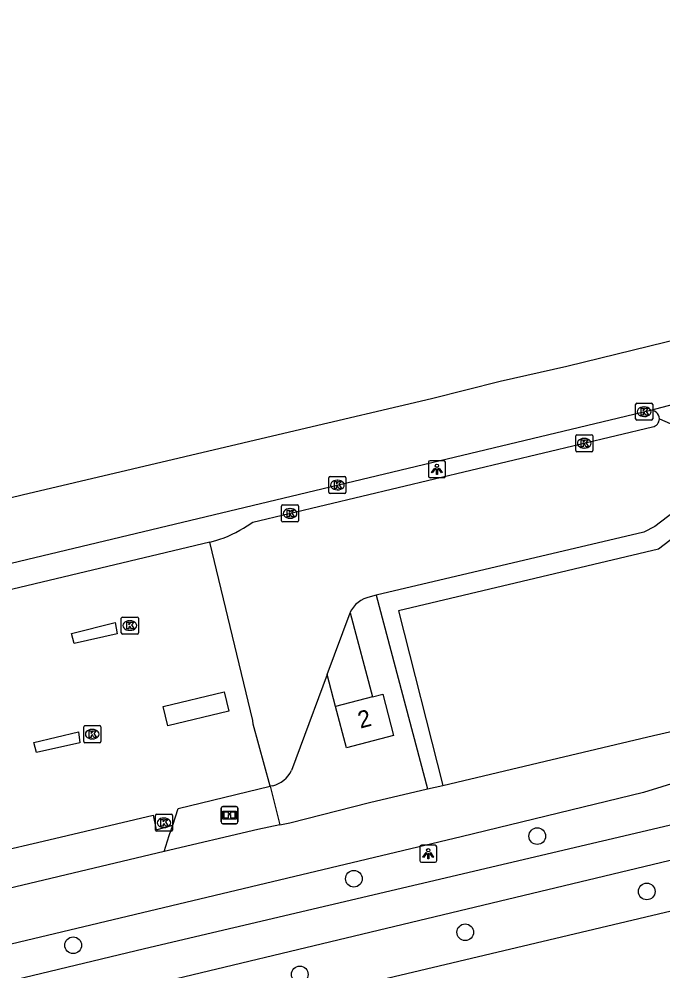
# Model space of a CAD drawing. Extents: x 157663 to 158496, y 379212 to 380934.
# Drawn here: x 158190.6 to 158228.4, y 380874.1 to 380929.9 of the extents above; entities that cross this region are included whole.
import ezdxf

# ---------------------------------------------------------------- set-up
doc = ezdxf.new("R2010")
doc.units = 0
for name, color, linetype in [('IMGEO_Boom', 7, 'Continuous'), ('IMGEO_Fietspad_gesloten', 7, 'Continuous'), ('IMGEO_Groenvoorziening', 7, 'Continuous'), ('IMGEO_Hek', 7, 'Continuous'), ('IMGEO_Informatiebord', 7, 'Continuous'), ('IMGEO_Kolk', 7, 'Continuous'), ('IMGEO_Lichtpunt', 7, 'Continuous'), ('IMGEO_Pand', 7, 'Continuous'), ('IMGEO_Pand_nummerreeks', 7, 'Continuous'), ('IMGEO_Rijbaan_lokaal_gesloten', 7, 'Continuous'), ('IMGEO_Rijbaan_lokaal_open', 7, 'Continuous'), ('IMGEO_Rijbaan_regionaal_gesloten', 7, 'Continuous'), ('IMGEO_Voetpad_halfverhard', 7, 'Continuous'), ('IMGEO_Voetpad_open', 7, 'Continuous')]:
    doc.layers.add(name, color=color, linetype=linetype)

msp = doc.modelspace()

# ---------------------------------------------------------------- linework, layer by layer
at = {"layer": 'IMGEO_Boom'}
for centre in [(158221.018, 380881.956), (158210.269, 380879.461), (158227.432, 380878.713), (158216.797, 380876.321), (158193.821, 380875.556), (158207.103, 380873.852)]:
    msp.add_circle(centre, 0.489, dxfattribs=at)
at = {"layer": 'IMGEO_Fietspad_gesloten'}
for points in [[(158214.584, 380884.721), (158215.49, 380884.935), (158221.487, 380886.347), (158227.823, 380887.854), (158228.952, 380888.114)], [(158234.764, 380886.844), (158227.239, 380884.51), (158216.562, 380881.917), (158176.169, 380872.274), (158170.786, 380871.038), (158169.397, 380870.904), (158167.571, 380870.872), (158165.75, 380871.003), (158163.948, 380871.297), (158155.69, 380872.659), (158150.365, 380873.521), (158148.523, 380873.783), (158145.729, 380873.832), (158142.943, 380873.632), (158141.381, 380873.409), (158125.611, 380869.701)], [(158205.929, 380882.622), (158206.509, 380882.744), (158211.181, 380883.92), (158214.584, 380884.721)], [(158205.929, 380882.622), (158204.633, 380882.349), (158199.155, 380881.064)], [(158199.155, 380881.064), (158186.759, 380878.107)]]:
    msp.add_lwpolyline(points, dxfattribs=at)
at = {"layer": 'IMGEO_Groenvoorziening'}
msp.add_lwpolyline([(158163.827, 380862.151), (158230.016, 380877.859)], dxfattribs=at)
at = {"layer": 'IMGEO_Hek'}
for points in [[(158236.116, 380904.381), (158234.153, 380903.401), (158228.121, 380898.781), (158212.895, 380895.165), (158215.49, 380884.935)], [(158204.633, 380882.349), (158199.155, 380881.064)], [(158199.155, 380881.064), (158186.759, 380878.107)]]:
    msp.add_lwpolyline(points, dxfattribs=at)
at = {"layer": 'IMGEO_Informatiebord'}
for p, q in [((158202.49, 380882.788), (158202.49, 380883.588)), ((158202.49, 380883.588), (158202.49, 380882.788)), ((158202.59, 380883.688), (158203.38, 380883.688)), ((158203.38, 380883.688), (158202.59, 380883.688)), ((158203.48, 380883.588), (158203.48, 380882.788)), ((158203.48, 380882.788), (158203.48, 380883.588)), ((158203.38, 380882.688), (158202.59, 380882.688)), ((158202.59, 380882.688), (158203.38, 380882.688))]:
    msp.add_line(p, q, dxfattribs=at)
for points in [[(158202.591, 380883.42), (158203.379, 380883.42), (158203.379, 380882.956), (158202.591, 380882.956), (158202.591, 380883.42)], [(158202.656, 380883.355), (158202.656, 380883.021), (158202.931, 380883.021), (158202.932, 380883.234), (158203.036, 380883.235), (158203.037, 380883.021), (158203.314, 380883.021), (158203.314, 380883.355), (158203.038, 380883.355), (158203.038, 380883.275), (158202.932, 380883.275), (158202.932, 380883.355), (158202.656, 380883.355)]]:
    msp.add_lwpolyline(points, dxfattribs=at)
for centre, start, end in [((158202.59, 380883.588), 90, 180), ((158202.59, 380883.588), 90, 180), ((158203.38, 380883.588), 0, 90), ((158203.38, 380883.588), 360, 90), ((158202.59, 380882.788), 180, 270), ((158202.59, 380882.788), 180, 270), ((158203.38, 380882.788), 270, 0), ((158203.38, 380882.788), 270, 0)]:
    msp.add_arc(centre, 0.1, start, end, dxfattribs=at)
at = {"layer": 'IMGEO_Kolk'}
for p, q in [((158226.782, 380906.416), (158226.782, 380907.268)), ((158226.857, 380907.342), (158227.709, 380907.342)), ((158227.27, 380907.122), (158227.295, 380907.122)), ((158227.783, 380907.268), (158227.783, 380906.416)), ((158227.293, 380906.562), (158227.268, 380906.562)), ((158227.709, 380906.342), (158226.857, 380906.342)), ((158223.271, 380904.567), (158223.271, 380905.419)), ((158223.346, 380905.493), (158224.198, 380905.493)), ((158224.272, 380905.419), (158224.272, 380904.567)), ((158223.759, 380905.273), (158223.784, 380905.273)), ((158224.198, 380904.493), (158223.346, 380904.493)), ((158223.782, 380904.713), (158223.757, 380904.713)), ((158208.805, 380902.116), (158208.805, 380902.968)), ((158208.88, 380903.042), (158209.732, 380903.042)), ((158209.293, 380902.822), (158209.318, 380902.822)), ((158209.806, 380902.968), (158209.806, 380902.116)), ((158209.732, 380902.042), (158208.88, 380902.042)), ((158209.316, 380902.262), (158209.291, 380902.262)), ((158206.033, 380900.453), (158206.033, 380901.305)), ((158206.108, 380901.379), (158206.96, 380901.379)), ((158206.521, 380901.159), (158206.546, 380901.159)), ((158207.034, 380901.305), (158207.034, 380900.453)), ((158206.96, 380900.379), (158206.108, 380900.379)), ((158206.544, 380900.599), (158206.519, 380900.599)), ((158196.716, 380894.804), (158197.568, 380894.804)), ((158196.641, 380893.878), (158196.641, 380894.73)), ((158197.129, 380894.584), (158197.154, 380894.584)), ((158197.642, 380894.73), (158197.642, 380893.878)), ((158197.568, 380893.804), (158196.716, 380893.804)), ((158197.152, 380894.024), (158197.127, 380894.024)), ((158194.437, 380887.509), (158194.437, 380888.361)), ((158194.512, 380888.435), (158195.364, 380888.435)), ((158194.925, 380888.215), (158194.95, 380888.215)), ((158195.438, 380888.361), (158195.438, 380887.509)), ((158194.948, 380887.655), (158194.923, 380887.655)), ((158195.364, 380887.435), (158194.512, 380887.435)), ((158198.644, 380882.314), (158198.644, 380883.166)), ((158198.719, 380883.24), (158199.571, 380883.24)), ((158199.645, 380883.166), (158199.645, 380882.314)), ((158199.132, 380883.02), (158199.157, 380883.02)), ((158199.571, 380882.24), (158198.719, 380882.24)), ((158199.155, 380882.46), (158199.13, 380882.46))]:
    msp.add_line(p, q, dxfattribs=at)
for points in [[(158226.782, 380906.416), (158226.782, 380907.268)], [(158226.857, 380907.342), (158227.709, 380907.342)], [(158227.103, 380907.042), (158227.226, 380907.042), (158227.226, 380906.891), (158227.356, 380907.042), (158227.52, 380907.042), (158227.374, 380906.891), (158227.527, 380906.642), (158227.375, 380906.642), (158227.29, 380906.806), (158227.226, 380906.739), (158227.226, 380906.642), (158227.103, 380906.642), (158227.103, 380907.042)], [(158227.783, 380907.268), (158227.783, 380906.416)], [(158227.709, 380906.342), (158226.857, 380906.342)], [(158223.271, 380904.567), (158223.271, 380905.419)], [(158223.346, 380905.493), (158224.198, 380905.493)], [(158224.272, 380905.419), (158224.272, 380904.567)], [(158223.592, 380905.193), (158223.715, 380905.193), (158223.715, 380905.042), (158223.845, 380905.193), (158224.009, 380905.193), (158223.863, 380905.042), (158224.016, 380904.793), (158223.864, 380904.793), (158223.779, 380904.957), (158223.715, 380904.89), (158223.715, 380904.793), (158223.592, 380904.793), (158223.592, 380905.193)], [(158224.198, 380904.493), (158223.346, 380904.493)], [(158208.805, 380902.116), (158208.805, 380902.968)], [(158208.88, 380903.042), (158209.732, 380903.042)], [(158209.126, 380902.742), (158209.249, 380902.742), (158209.249, 380902.591), (158209.379, 380902.742), (158209.543, 380902.742), (158209.397, 380902.591), (158209.55, 380902.342), (158209.398, 380902.342), (158209.313, 380902.506), (158209.249, 380902.439), (158209.249, 380902.342), (158209.126, 380902.342), (158209.126, 380902.742)], [(158209.806, 380902.968), (158209.806, 380902.116)], [(158209.732, 380902.042), (158208.88, 380902.042)], [(158206.033, 380900.453), (158206.033, 380901.305)], [(158206.108, 380901.379), (158206.96, 380901.379)], [(158206.354, 380901.079), (158206.477, 380901.079), (158206.477, 380900.928), (158206.607, 380901.079), (158206.771, 380901.079), (158206.625, 380900.928), (158206.778, 380900.679), (158206.626, 380900.679), (158206.541, 380900.843), (158206.477, 380900.776), (158206.477, 380900.679), (158206.354, 380900.679), (158206.354, 380901.079)], [(158207.034, 380901.305), (158207.034, 380900.453)], [(158206.96, 380900.379), (158206.108, 380900.379)], [(158196.716, 380894.804), (158197.568, 380894.804)], [(158196.641, 380893.878), (158196.641, 380894.73)], [(158196.962, 380894.504), (158197.085, 380894.504), (158197.085, 380894.353), (158197.215, 380894.504), (158197.379, 380894.504), (158197.233, 380894.353), (158197.386, 380894.104), (158197.234, 380894.104), (158197.149, 380894.268), (158197.085, 380894.201), (158197.085, 380894.104), (158196.962, 380894.104), (158196.962, 380894.504)], [(158197.642, 380894.73), (158197.642, 380893.878)], [(158197.568, 380893.804), (158196.716, 380893.804)], [(158194.437, 380887.509), (158194.437, 380888.361)], [(158194.512, 380888.435), (158195.364, 380888.435)], [(158194.758, 380888.135), (158194.881, 380888.135), (158194.881, 380887.984), (158195.011, 380888.135), (158195.175, 380888.135), (158195.029, 380887.984), (158195.182, 380887.735), (158195.03, 380887.735), (158194.945, 380887.899), (158194.881, 380887.832), (158194.881, 380887.735), (158194.758, 380887.735), (158194.758, 380888.135)], [(158195.438, 380888.361), (158195.438, 380887.509)], [(158195.364, 380887.435), (158194.512, 380887.435)], [(158198.644, 380882.314), (158198.644, 380883.166)], [(158198.719, 380883.24), (158199.571, 380883.24)], [(158199.645, 380883.166), (158199.645, 380882.314)], [(158198.965, 380882.94), (158199.088, 380882.94), (158199.088, 380882.789), (158199.218, 380882.94), (158199.382, 380882.94), (158199.236, 380882.789), (158199.389, 380882.54), (158199.237, 380882.54), (158199.152, 380882.704), (158199.088, 380882.637), (158199.088, 380882.54), (158198.965, 380882.54), (158198.965, 380882.94)], [(158199.571, 380882.24), (158198.719, 380882.24)]]:
    msp.add_lwpolyline(points, dxfattribs=at)
for centre, start, end in [((158226.859, 380907.266), 91.552, 178.448), ((158226.859, 380907.266), 91.552, 178.448), ((158227.707, 380907.266), 1.552, 88.448), ((158227.707, 380907.266), 1.552, 88.448), ((158226.859, 380906.418), 181.552, 268.448), ((158226.859, 380906.418), 181.552, 268.448), ((158227.707, 380906.418), 271.552, 358.448), ((158227.707, 380906.418), 271.552, 358.448), ((158223.348, 380905.417), 91.552, 178.448), ((158223.348, 380905.417), 91.552, 178.448), ((158224.196, 380905.417), 1.552, 88.448), ((158224.196, 380905.417), 1.552, 88.448), ((158223.348, 380904.569), 181.552, 268.448), ((158223.348, 380904.569), 181.552, 268.448), ((158224.196, 380904.569), 271.552, 358.448), ((158224.196, 380904.569), 271.552, 358.448), ((158208.882, 380902.966), 91.552, 178.448), ((158208.882, 380902.966), 91.552, 178.448), ((158209.73, 380902.966), 1.552, 88.448), ((158209.73, 380902.966), 1.552, 88.448), ((158208.882, 380902.118), 181.552, 268.448), ((158208.882, 380902.118), 181.552, 268.448), ((158209.73, 380902.118), 271.552, 358.448), ((158209.73, 380902.118), 271.552, 358.448), ((158206.11, 380901.303), 91.552, 178.448), ((158206.11, 380901.303), 91.552, 178.448), ((158206.958, 380901.303), 1.552, 88.448), ((158206.958, 380901.303), 1.552, 88.448), ((158206.11, 380900.455), 181.552, 268.448), ((158206.11, 380900.455), 181.552, 268.448), ((158206.958, 380900.455), 271.552, 358.448), ((158206.958, 380900.455), 271.552, 358.448), ((158196.718, 380894.728), 91.552, 178.448), ((158196.718, 380894.728), 91.552, 178.448), ((158197.566, 380894.728), 1.552, 88.448), ((158197.566, 380894.728), 1.552, 88.448), ((158196.718, 380893.88), 181.552, 268.448), ((158196.718, 380893.88), 181.552, 268.448), ((158197.566, 380893.88), 271.552, 358.448), ((158197.566, 380893.88), 271.552, 358.448), ((158194.514, 380888.359), 91.552, 178.448), ((158194.514, 380888.359), 91.552, 178.448), ((158195.362, 380888.359), 1.552, 88.448), ((158195.362, 380888.359), 1.552, 88.448), ((158194.514, 380887.511), 181.552, 268.448), ((158194.514, 380887.511), 181.552, 268.448), ((158195.362, 380887.511), 271.552, 358.448), ((158195.362, 380887.511), 271.552, 358.448), ((158198.721, 380883.164), 91.552, 178.448), ((158198.721, 380883.164), 91.552, 178.448), ((158199.569, 380883.164), 1.552, 88.448), ((158199.569, 380883.164), 1.552, 88.448), ((158198.721, 380882.316), 181.552, 268.448), ((158198.721, 380882.316), 181.552, 268.448), ((158199.569, 380882.316), 271.552, 358.448), ((158199.569, 380882.316), 271.552, 358.448)]:
    msp.add_arc(centre, 0.0765, start, end, dxfattribs=at)
for centre, major_axis, ratio, start_param, end_param in [((158227.269, 380906.842), (-0.387, 0.002), 0.722429, 4.712389, 7.853982), ((158227.294, 380906.842), (-0.39, 0.002), 0.717154, 1.570796, 4.712389), ((158223.758, 380904.993), (-0.387, 0.002), 0.722429, 4.712389, 7.853982), ((158223.783, 380904.993), (-0.39, 0.002), 0.717154, 1.570796, 4.712389), ((158209.292, 380902.542), (-0.387, 0.002), 0.722429, 4.712389, 7.853982), ((158209.317, 380902.542), (-0.39, 0.002), 0.717154, 1.570796, 4.712389), ((158206.52, 380900.879), (-0.387, 0.002), 0.722429, 4.712389, 7.853982), ((158206.545, 380900.879), (-0.39, 0.002), 0.717154, 1.570796, 4.712389), ((158197.128, 380894.304), (-0.387, 0.002), 0.722429, 4.712389, 7.853982), ((158197.153, 380894.304), (-0.39, 0.002), 0.717154, 1.570796, 4.712389), ((158194.924, 380887.935), (-0.387, 0.002), 0.722429, 4.712389, 7.853982), ((158194.949, 380887.935), (-0.39, 0.002), 0.717154, 1.570796, 4.712389), ((158199.131, 380882.74), (-0.387, 0.002), 0.722429, 4.712389, 7.853982), ((158199.156, 380882.74), (-0.39, 0.002), 0.717154, 1.570796, 4.712389)]:
    msp.add_ellipse(centre, major_axis=major_axis, ratio=ratio, start_param=start_param, end_param=end_param, dxfattribs=at)
at = {"layer": 'IMGEO_Lichtpunt'}
for p, q in [((158214.639, 380903.877), (158214.639, 380903.07)), ((158214.639, 380903.877), (158214.639, 380903.07)), ((158215.541, 380903.972), (158214.733, 380903.972)), ((158215.541, 380903.972), (158214.733, 380903.972)), ((158215.635, 380903.07), (158215.635, 380903.877)), ((158215.635, 380903.07), (158215.635, 380903.877)), ((158214.733, 380902.976), (158215.541, 380902.976)), ((158214.733, 380902.976), (158215.541, 380902.976)), ((158215.035, 380881.425), (158214.227, 380881.425)), ((158215.035, 380881.425), (158214.227, 380881.425)), ((158214.133, 380881.33), (158214.133, 380880.523)), ((158214.133, 380881.33), (158214.133, 380880.523)), ((158215.129, 380880.523), (158215.129, 380881.33)), ((158215.129, 380880.523), (158215.129, 380881.33)), ((158214.227, 380880.429), (158215.035, 380880.429)), ((158214.227, 380880.429), (158215.035, 380880.429))]:
    msp.add_line(p, q, dxfattribs=at)
for points in [[(158215.013, 380903.541), (158215.052, 380903.513), (158214.864, 380903.251), (158214.826, 380903.278), (158215.013, 380903.541)], [(158215.115, 380903.493), (158215.162, 380903.493), (158215.162, 380903.171), (158215.115, 380903.171), (158215.115, 380903.493)], [(158215.225, 380903.513), (158215.263, 380903.54), (158215.45, 380903.278), (158215.411, 380903.25), (158215.225, 380903.513)], [(158214.507, 380880.994), (158214.546, 380880.966), (158214.358, 380880.704), (158214.32, 380880.731), (158214.507, 380880.994)], [(158214.609, 380880.946), (158214.656, 380880.946), (158214.656, 380880.624), (158214.609, 380880.624), (158214.609, 380880.946)], [(158214.719, 380880.966), (158214.757, 380880.993), (158214.944, 380880.731), (158214.905, 380880.703), (158214.719, 380880.966)]]:
    msp.add_lwpolyline(points, dxfattribs=at)
for centre in [(158215.138, 380903.675), (158214.632, 380881.128)]:
    msp.add_circle(centre, 0.0994, dxfattribs=at)
for centre, start, end in [((158214.733, 380903.877), 90, 180), ((158214.733, 380903.877), 90, 180), ((158215.541, 380903.877), 0, 90), ((158215.541, 380903.877), 0, 90), ((158214.733, 380903.07), 180, 270), ((158214.733, 380903.07), 180, 270), ((158215.541, 380903.07), 270, 0), ((158215.541, 380903.07), 270, 360), ((158214.227, 380881.33), 90, 180), ((158214.227, 380881.33), 90, 180), ((158215.035, 380881.33), 0, 90), ((158215.035, 380881.33), 0, 90), ((158214.227, 380880.523), 180, 270), ((158214.227, 380880.523), 180, 270), ((158215.035, 380880.523), 270, 0), ((158215.035, 380880.523), 270, 360)]:
    msp.add_arc(centre, 0.0946, start, end, dxfattribs=at)
at = {"layer": 'IMGEO_Pand'}
for points in [[(158211.367, 380890.125), (158211.959, 380890.28), (158212.594, 380887.85), (158209.837, 380887.13), (158209.202, 380889.559)], [(158211.367, 380890.125), (158209.202, 380889.559)]]:
    msp.add_lwpolyline(points, dxfattribs=at)
at = {"layer": 'IMGEO_Rijbaan_lokaal_gesloten'}
for points in [[(158201.827, 380899.202), (158188.963, 380896.127), (158185.622, 380895.329)], [(158205.367, 380884.878), (158204.377, 380888.514), (158204.341, 380888.738), (158201.827, 380899.202)], [(158193.876, 380893.253), (158193.721, 380893.848), (158196.28, 380894.475), (158196.391, 380893.823), (158193.876, 380893.253)], [(158202.675, 380890.413), (158202.946, 380889.285), (158199.367, 380888.427), (158199.097, 380889.556), (158202.675, 380890.413)], [(158194.204, 380887.436), (158191.667, 380886.86), (158191.515, 380887.455), (158194.124, 380888.068), (158194.204, 380887.436)], [(158199.653, 380882.597), (158199.974, 380883.586), (158205.367, 380884.878)], [(158189.039, 380880.951), (158192.403, 380881.745), (158198.513, 380883.189), (158198.683, 380882.333), (158199.653, 380882.597)]]:
    msp.add_lwpolyline(points, dxfattribs=at)
at = {"layer": 'IMGEO_Rijbaan_lokaal_open'}
for points in [[(158204.015, 380900.159), (158204.341, 380900.357), (158227.779, 380905.95)], [(158233.252, 380904.195), (158227.91, 380900.104), (158227.265, 380899.78), (158211.577, 380896.08)], [(158201.827, 380899.202), (158202.18, 380899.286)], [(158211.577, 380896.08), (158211.221, 380895.986)], [(158208.702, 380891.44), (158210.044, 380895.05)], [(158208.702, 380891.44), (158207.116, 380887.172), (158206.606, 380885.799)], [(158205.516, 380884.914), (158205.367, 380884.878)]]:
    msp.add_lwpolyline(points, dxfattribs=at)
for centre, radius, start, end in [((158227.683, 380906.431), 0.491, 281.2455, 359.2621), ((158200.224, 380905.763), 6.766, 286.8062, 304.0792), ((158211.524, 380894.397), 1.618, 100.7935, 156.1929), ((158205.134, 380886.499), 1.63, 283.565, 334.5832)]:
    msp.add_arc(centre, radius, start, end, dxfattribs=at)
at = {"layer": 'IMGEO_Rijbaan_regionaal_gesloten'}
for points in [[(158227.57, 380906.91), (158227.589, 380906.916), (158234.792, 380908.812), (158245.832, 380911.345), (158257.255, 380914.069), (158264.922, 380915.897), (158276.489, 380918.656), (158285.916, 380920.974), (158295.501, 380923.229), (158305.087, 380925.483), (158312.504, 380927.227), (158323.73, 380929.867)], [(158137.39, 380890.404), (158142.255, 380891.198), (158146.534, 380891.945), (158150.8, 380892.763), (158154.938, 380893.603), (158162.936, 380895.386), (158167.147, 380896.325), (158170.912, 380897.206), (158174.94, 380898.189), (158178.87, 380899.085), (158182.9, 380900.059), (158186.862, 380901.016), (158190.824, 380901.973), (158206.828, 380905.74), (158214.827, 380907.623), (158218.848, 380908.629), (158222.755, 380909.522), (158230.487, 380911.415)], [(158178.332, 380895.132), (158227.57, 380906.91)], [(158228.174, 380906.425), (158233.252, 380904.195)]]:
    msp.add_lwpolyline(points, dxfattribs=at)
msp.add_arc((158227.683, 380906.432), 0.492, 359.2392, 103.2332, dxfattribs=at)
at = {"layer": 'IMGEO_Voetpad_halfverhard'}
msp.add_lwpolyline([(158211.577, 380896.08), (158214.584, 380884.721)], dxfattribs=at)
at = {"layer": 'IMGEO_Voetpad_open'}
for points in [[(158165.296, 380869.194), (158168.609, 380869.132), (158171.914, 380869.367), (158175.184, 380869.895), (158175.796, 380870.028), (158198.003, 380875.375), (158230.074, 380882.921), (158233.565, 380883.858), (158235.501, 380884.527), (158238.669, 380885.752), (158241.715, 380887.254), (158242.343, 380887.608), (158251.028, 380892.001), (158253.448, 380893.203), (158256.213, 380894.388), (158260.568, 380895.884), (158269.34, 380898.007)], [(158210.044, 380895.05), (158211.367, 380890.125)], [(158209.202, 380889.559), (158208.702, 380891.44)], [(158205.367, 380884.878), (158205.717, 380883.473), (158205.929, 380882.622)], [(158199.155, 380881.064), (158199.456, 380881.991), (158199.653, 380882.597)], [(158231.096, 380881.082), (158178.582, 380868.481), (158173.991, 380867.557), (158171.184, 380867.259), (158167.176, 380867), (158165.172, 380867.015)]]:
    msp.add_lwpolyline(points, dxfattribs=at)

# ---------------------------------------------------------------- texts
at = {"layer": 'IMGEO_Pand_nummerreeks'}
msp.add_text('2', height=1, rotation=14.642, dxfattribs=at).set_placement((158210.651, 380888.259))

doc.saveas('drawing.dxf')
